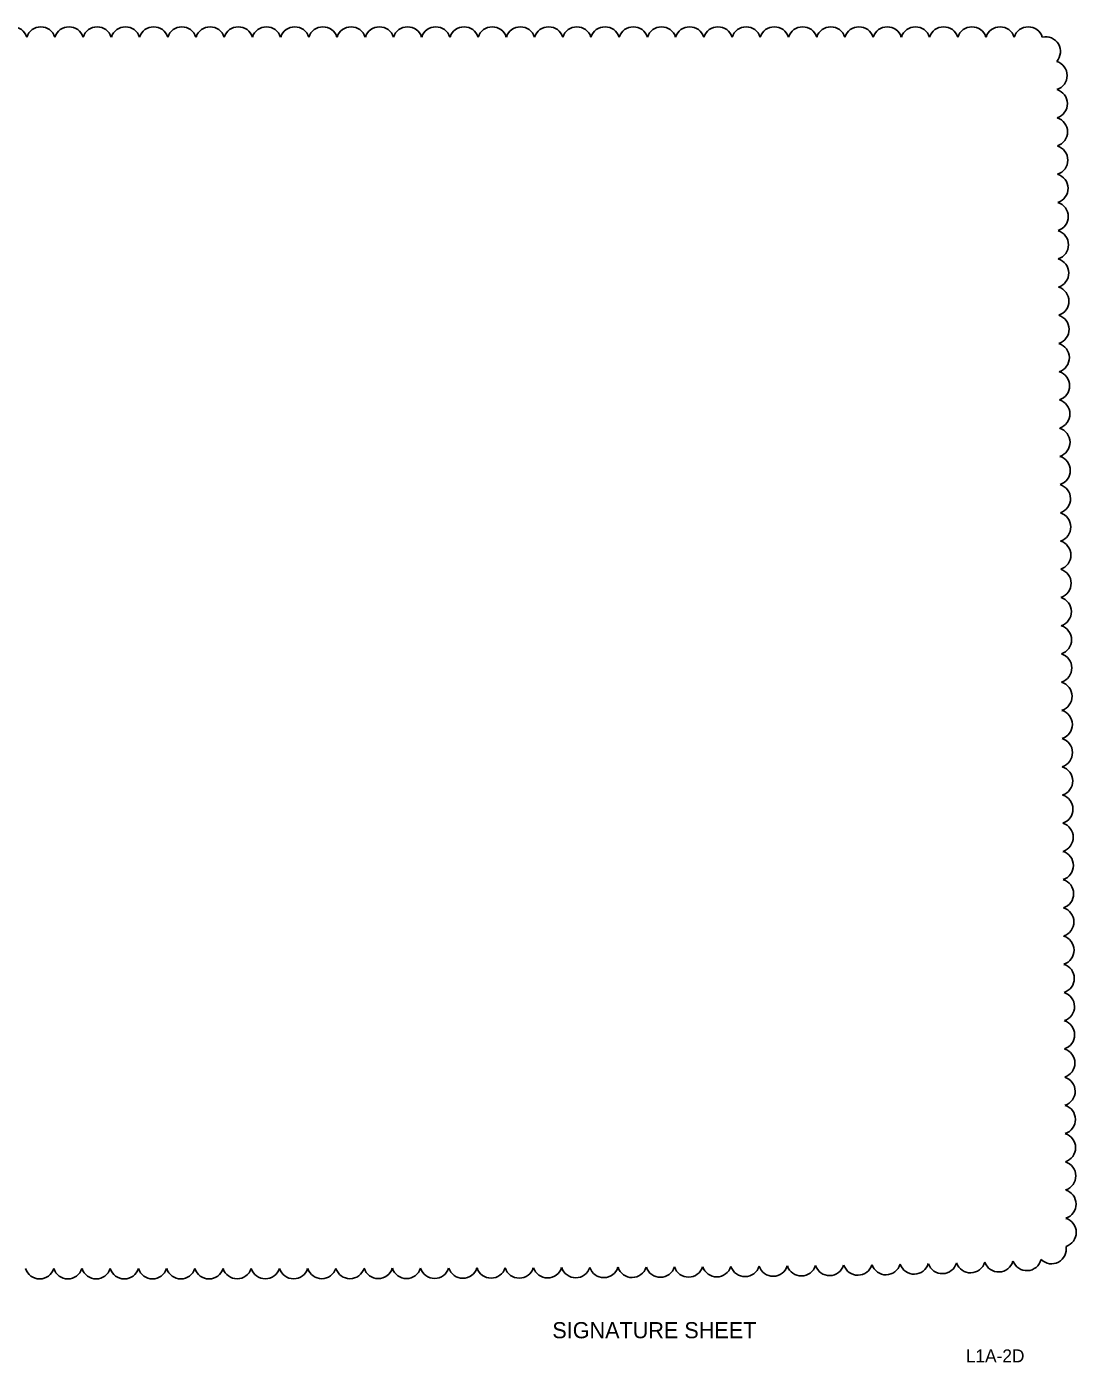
# Model space of a CAD drawing. Extents: x -811.2 to -795.1, y -2226.2 to -2215.9.
# Drawn here: x -803.27 to -795.14, y -2226.21 to -2215.88 of the extents above; entities that cross this region are included whole.
import ezdxf

# ---------------------------------------------------------------- set-up
doc = ezdxf.new("R2010")
doc.units = 0
for name, color, linetype in [('Cloud_dp', 7, 'Continuous'), ('TextMisc', 7, 'Continuous'), ('TextShtNo', 7, 'Continuous')]:
    doc.layers.add(name, color=color, linetype=linetype)

msp = doc.modelspace()

# ---------------------------------------------------------------- linework, layer by layer
at = {"layer": 'Cloud_dp'}
for centre, start, end in [((-803.375, -2215.992), 17.5009, 162.5009), ((-803.157, -2215.992), 17.5, 162.5), ((-802.939, -2215.992), 17.5, 162.5), ((-802.721, -2215.992), 17.5, 162.5), ((-802.502, -2215.992), 17.5, 162.5), ((-802.284, -2215.992), 17.5, 162.5), ((-802.066, -2215.992), 17.5, 162.5), ((-801.847, -2215.992), 17.5, 162.5), ((-801.629, -2215.992), 17.5, 162.5), ((-801.411, -2215.992), 17.5, 162.5), ((-801.192, -2215.992), 17.5, 162.5), ((-800.974, -2215.992), 17.5, 162.5), ((-800.756, -2215.992), 17.5, 162.5), ((-800.537, -2215.992), 17.5, 162.5), ((-800.319, -2215.992), 17.5, 162.5), ((-800.101, -2215.992), 17.5, 162.5), ((-799.882, -2215.992), 17.5, 162.5), ((-799.664, -2215.992), 17.5, 162.5), ((-799.446, -2215.992), 17.5, 162.5), ((-799.227, -2215.992), 17.5, 162.5), ((-799.009, -2215.992), 17.5, 162.5), ((-798.791, -2215.992), 17.5, 162.5), ((-798.572, -2215.992), 17.5, 162.5), ((-798.354, -2215.992), 17.5, 162.5), ((-798.136, -2215.992), 17.5, 162.5), ((-797.917, -2215.992), 17.5, 162.5), ((-797.699, -2215.992), 17.5, 162.5), ((-797.481, -2215.992), 17.5, 162.5), ((-797.262, -2215.992), 17.5, 162.5), ((-797.044, -2215.992), 17.5, 162.5), ((-796.826, -2215.992), 17.5, 162.5), ((-796.607, -2215.992), 17.5, 162.5), ((-796.389, -2215.992), 17.5, 162.5), ((-796.171, -2215.992), 17.5, 162.5), ((-795.952, -2215.992), 17.5, 162.5), ((-795.734, -2215.992), 17.5, 162.5), ((-795.516, -2215.992), 17.5, 162.5), ((-795.381, -2216.069), 318.1116, 103.1116), ((-795.329, -2216.255), 287.9529, 72.9529), ((-795.327, -2216.473), 287.9529, 72.9529), ((-795.326, -2216.691), 287.9529, 72.9529), ((-795.324, -2216.91), 287.9529, 72.9529), ((-795.322, -2217.128), 287.9529, 72.9529), ((-795.32, -2217.346), 287.9529, 72.9529), ((-795.319, -2217.565), 287.9529, 72.9529), ((-795.317, -2217.783), 287.9529, 72.9529), ((-795.315, -2218.001), 287.9529, 72.9529), ((-795.314, -2218.219), 287.9529, 72.9529), ((-795.312, -2218.438), 287.9529, 72.9529), ((-795.31, -2218.656), 287.9529, 72.9529), ((-795.308, -2218.874), 287.9529, 72.9529), ((-795.307, -2219.093), 287.9529, 72.9529), ((-795.305, -2219.311), 287.9529, 72.9529), ((-795.303, -2219.529), 287.9529, 72.9529), ((-795.301, -2219.748), 287.9529, 72.9529), ((-795.3, -2219.966), 287.9529, 72.9529), ((-795.298, -2220.184), 287.9529, 72.9529), ((-795.296, -2220.403), 287.9529, 72.9529), ((-795.295, -2220.621), 287.9529, 72.9529), ((-795.293, -2220.839), 287.9527, 72.9527), ((-795.291, -2221.058), 287.9524, 72.9524), ((-795.289, -2221.276), 287.9521, 72.9521), ((-795.288, -2221.494), 287.9519, 72.9519), ((-795.286, -2221.713), 287.9515, 72.9515), ((-795.284, -2221.931), 287.9512, 72.9512), ((-795.282, -2222.149), 287.9508, 72.9508), ((-795.281, -2222.367), 287.9504, 72.9504), ((-795.279, -2222.586), 287.9499, 72.9499), ((-795.277, -2222.804), 287.9494, 72.9494), ((-795.276, -2223.022), 287.9488, 72.9488), ((-795.274, -2223.241), 287.9481, 72.9481), ((-795.272, -2223.459), 287.9473, 72.9473), ((-795.271, -2223.677), 287.9464, 72.9464), ((-795.269, -2223.896), 287.9452, 72.9452), ((-795.267, -2224.114), 287.9438, 72.9438), ((-795.265, -2224.332), 287.9419, 72.9419), ((-795.264, -2224.551), 287.9394, 72.9394), ((-795.262, -2224.769), 287.9355, 72.9355), ((-795.26, -2224.987), 287.9288, 72.9288), ((-795.259, -2225.206), 287.9106, 72.9106), ((-795.336, -2225.335), 225.4798, 10.4798), ((-795.527, -2225.388), 200.5167, 345.5167), ((-803.166, -2225.452), 197.496, 342.496), ((-802.948, -2225.452), 197.5011, 342.5011), ((-802.729, -2225.452), 197.5111, 342.5111), ((-802.511, -2225.452), 197.522, 342.522), ((-802.293, -2225.452), 197.5335, 342.5335), ((-802.074, -2225.452), 197.5456, 342.5456), ((-801.856, -2225.452), 197.5582, 342.5582), ((-801.638, -2225.451), 197.5715, 342.5715), ((-801.42, -2225.451), 197.5855, 342.5855), ((-801.201, -2225.451), 197.6002, 342.6002), ((-800.983, -2225.45), 197.6157, 342.6157), ((-800.765, -2225.45), 197.6322, 342.6322), ((-800.546, -2225.449), 197.6497, 342.6497), ((-800.328, -2225.449), 197.6683, 342.6683), ((-800.11, -2225.448), 197.6881, 342.6881), ((-799.891, -2225.447), 197.7093, 342.7093), ((-799.673, -2225.446), 197.732, 342.732), ((-799.455, -2225.446), 197.7565, 342.7565), ((-799.236, -2225.444), 197.7829, 342.7829), ((-799.018, -2225.443), 197.8116, 342.8116), ((-798.8, -2225.442), 197.8429, 342.8429), ((-798.582, -2225.441), 197.8771, 342.8771), ((-798.363, -2225.439), 197.9149, 342.9149), ((-798.145, -2225.438), 197.9569, 342.9569), ((-797.927, -2225.436), 198.0039, 343.0039), ((-797.708, -2225.434), 198.0569, 343.0569), ((-797.49, -2225.431), 198.1174, 343.1174), ((-797.272, -2225.429), 198.1874, 343.1874), ((-797.054, -2225.426), 198.2696, 343.2696), ((-796.835, -2225.423), 198.368, 343.368), ((-796.617, -2225.42), 198.4888, 343.4888), ((-796.399, -2225.415), 198.642, 343.642), ((-796.181, -2225.411), 198.8454, 343.8454), ((-795.963, -2225.405), 199.1345, 344.1345), ((-795.745, -2225.398), 199.5943, 344.5943)]:
    msp.add_arc(centre, 0.114, start, end, dxfattribs=at)

# ---------------------------------------------------------------- texts
at = {"layer": 'TextMisc'}
msp.add_text('       SIGNATURE SHEET         ', height=0.125, dxfattribs=at).set_placement((-799.524, -2226.025))
at = {"layer": 'TextShtNo'}
msp.add_text('L1A-2D', height=0.1, dxfattribs=at).set_placement((-795.999, -2226.211))

doc.saveas('drawing.dxf')
